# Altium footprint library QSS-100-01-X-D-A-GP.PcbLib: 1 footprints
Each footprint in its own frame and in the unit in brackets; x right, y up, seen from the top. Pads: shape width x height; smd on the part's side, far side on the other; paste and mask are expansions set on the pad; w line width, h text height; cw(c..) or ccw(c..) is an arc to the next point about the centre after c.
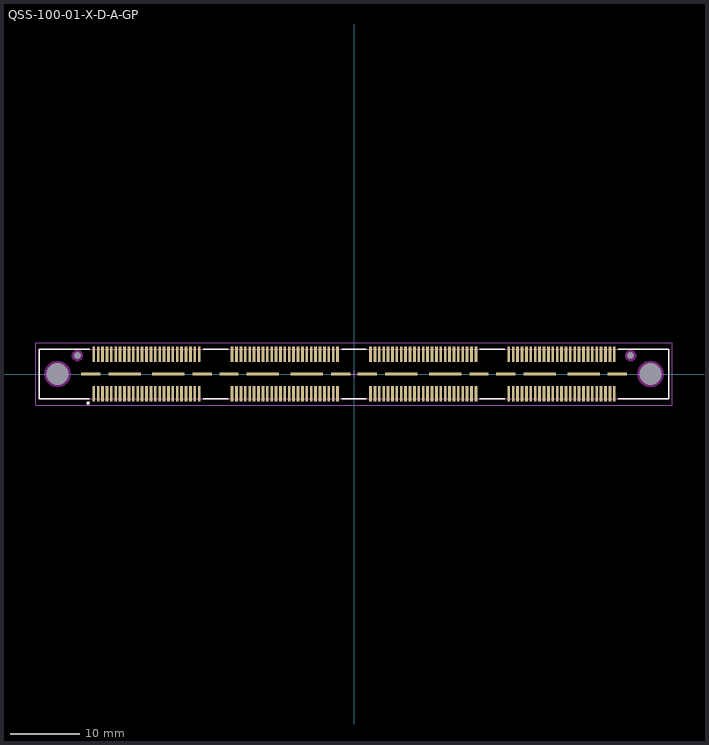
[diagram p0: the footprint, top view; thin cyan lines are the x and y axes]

## QSS-100-01-X-D-A-GP [mm] "0.635mm pitch, 200 pin, high speed socket; w/alignment pins"
height 3.63
pads (220):
  rect 0.4x2.25 smd mask+0: 1(-37.621,-2.865) 2(-37.621,2.865) 3(-36.986,-2.865) 4(-36.986,2.865) 5(-36.351,-2.865) 6(-36.351,2.865) 7(-35.716,-2.865) 8(-35.716,2.865) 9(-35.081,-2.865) 10(-35.081,2.865) 11(-34.446,-2.865) 12(-34.446,2.865) 13(-33.811,-2.865) 14(-33.811,2.865) 15(-33.176,-2.865) 16(-33.176,2.865) 17(-32.541,-2.865) 18(-32.541,2.865) 19(-31.906,-2.865) 20(-31.906,2.865) 21(-31.271,-2.865) 22(-31.271,2.865) 23(-30.636,-2.865) 24(-30.636,2.865) 25(-30.001,-2.865) 26(-30.001,2.865) 27(-29.366,-2.865) 28(-29.366,2.865) 29(-28.731,-2.865) 30(-28.731,2.865) 31(-28.096,-2.865) 32(-28.096,2.865) 33(-27.461,-2.865) 34(-27.461,2.865) 35(-26.826,-2.865) 36(-26.826,2.865) 37(-26.191,-2.865) 38(-26.191,2.865) 39(-25.556,-2.865) 40(-25.556,2.865) 41(-24.921,-2.865) 42(-24.921,2.865) 43(-24.286,-2.865) 44(-24.286,2.865) 45(-23.651,-2.865) 46(-23.651,2.865) 47(-23.016,-2.865) 48(-23.016,2.865) 49(-22.381,-2.865) 50(-22.381,2.865) 51(-17.619,-2.865) 52(-17.619,2.865) 53(-16.984,-2.865) 54(-16.984,2.865) 55(-16.349,-2.865) 56(-16.349,2.865) 57(-15.714,-2.865) 58(-15.714,2.865) 59(-15.079,-2.865) 60(-15.079,2.865) 61(-14.444,-2.865) 62(-14.444,2.865) 63(-13.809,-2.865) 64(-13.809,2.865) 65(-13.174,-2.865) 66(-13.174,2.865) 67(-12.539,-2.865) 68(-12.539,2.865) 69(-11.904,-2.865) 70(-11.904,2.865) 71(-11.269,-2.865) 72(-11.269,2.865) 73(-10.634,-2.865) 74(-10.634,2.865) 75(-9.999,-2.865) 76(-9.999,2.865) 77(-9.364,-2.865) 78(-9.364,2.865) 79(-8.729,-2.865) 80(-8.729,2.865) 81(-8.094,-2.865) 82(-8.094,2.865) 83(-7.459,-2.865) 84(-7.459,2.865) 85(-6.824,-2.865) 86(-6.824,2.865) 87(-6.189,-2.865) 88(-6.189,2.865) 89(-5.554,-2.865) 90(-5.554,2.865) 91(-4.919,-2.865) 92(-4.919,2.865) 93(-4.284,-2.865) 94(-4.284,2.865) 95(-3.649,-2.865) 96(-3.649,2.865) 97(-3.014,-2.865) 98(-3.014,2.865) 99(-2.379,-2.865) 100(-2.379,2.865) 101(2.384,-2.865) 102(2.384,2.865) 103(3.019,-2.865) 104(3.019,2.865) 105(3.654,-2.865) 106(3.654,2.865) 107(4.289,-2.865) 108(4.289,2.865) 109(4.924,-2.865) 110(4.924,2.865) 111(5.559,-2.865) 112(5.559,2.865) 113(6.194,-2.865) 114(6.194,2.865) 115(6.829,-2.865) 116(6.829,2.865) 117(7.464,-2.865) 118(7.464,2.865) 119(8.099,-2.865) 120(8.099,2.865) 121(8.734,-2.865) 122(8.734,2.865) 123(9.369,-2.865) 124(9.369,2.865) 125(10.004,-2.865) 126(10.004,2.865) 127(10.639,-2.865) 128(10.639,2.865) 129(11.274,-2.865) 130(11.274,2.865) 131(11.909,-2.865) 132(11.909,2.865) 133(12.544,-2.865) 134(12.544,2.865) 135(13.179,-2.865) 136(13.179,2.865) 137(13.814,-2.865) 138(13.814,2.865) 139(14.449,-2.865) 140(14.449,2.865) 141(15.084,-2.865) 142(15.084,2.865) 143(15.719,-2.865) 144(15.719,2.865) 145(16.354,-2.865) 146(16.354,2.865) 147(16.989,-2.865) 148(16.989,2.865) 149(17.624,-2.865) 150(17.624,2.865) 151(22.386,-2.865) 152(22.386,2.865) 153(23.021,-2.865) 154(23.021,2.865) 155(23.656,-2.865) 156(23.656,2.865) 157(24.291,-2.865) 158(24.291,2.865) 159(24.926,-2.865) 160(24.926,2.865) 161(25.561,-2.865) 162(25.561,2.865) 163(26.196,-2.865) 164(26.196,2.865) 165(26.831,-2.865) 166(26.831,2.865) 167(27.466,-2.865) 168(27.466,2.865) 169(28.101,-2.865) 170(28.101,2.865) 171(28.736,-2.865) 172(28.736,2.865) 173(29.371,-2.865) 174(29.371,2.865) 175(30.006,-2.865) 176(30.006,2.865) 177(30.641,-2.865) 178(30.641,2.865) 179(31.276,-2.865) 180(31.276,2.865) 181(31.911,-2.865) 182(31.911,2.865) 183(32.546,-2.865) 184(32.546,2.865) 185(33.181,-2.865) 186(33.181,2.865) 187(33.816,-2.865) 188(33.816,2.865) 189(34.451,-2.865) 190(34.451,2.865) 191(35.086,-2.865) 192(35.086,2.865) 193(35.721,-2.865) 194(35.721,2.865) 195(36.356,-2.865) 196(36.356,2.865) 197(36.991,-2.865) 198(36.991,2.865) 199(37.626,-2.865) 200(37.626,2.865)
  rect 2.8x0.45 smd mask+0: 201(-38.066,0) 204(-21.937,0) 205(-18.063,0) 208(-1.934,0) 209(1.939,0) 212(18.068,0) 213(21.942,0) 216(38.071,0)
  rect 4.7x0.45 smd mask+0: 202(-33.176,0) 203(-26.826,0) 206(-13.174,0) 207(-6.824,0) 210(6.829,0) 211(13.179,0) 214(26.831,0) 215(33.181,0)
  round 0.5 hole 3.2 unplated mask+0: 217(-42.86,0) 218(42.86,0)
  round 0.5 hole 1 unplated mask+0: 219(-40.004,2.657) 220(39.996,2.657)
Top Overlay:
  circle w0.25: c-38.45,-4.2 r0.125
  lines w0.2: -38.3,-3.6 -45.5,-3.6 -45.5,3.6 -38.2,3.6 ; -21.8,-3.6 -18.2,-3.6 ; -21.8,3.6 -18.2,3.6 ; -1.8,-3.6 1.8,-3.6 ; -1.8,3.6 1.8,3.6 ; 18.2,-3.6 21.8,-3.6 ; 18.2,3.6 21.8,3.6 ; 38.2,-3.6 45.5,-3.6 45.5,3.6 38.2,3.6
Keep-Out Layer:
  pour cut-out: -39.197,2.657 -39.225,2.866 -39.305,3.06 -39.433,3.228 -39.601,3.356 -39.795,3.436 -40.004,3.464 -40.213,3.436 -40.407,3.356 -40.575,3.228 -40.703,3.06 -40.783,2.866 -40.811,2.657 -40.783,2.448 -40.703,2.254 -40.575,2.086 -40.407,1.958 -40.213,1.878 -40.004,1.85 -39.795,1.878 -39.601,1.958 -39.433,2.086 -39.305,2.254 -39.225,2.448
  pour cut-out: 40.803,2.657 40.775,2.866 40.695,3.06 40.567,3.228 40.399,3.356 40.205,3.436 39.996,3.464 39.787,3.436 39.593,3.356 39.425,3.228 39.297,3.06 39.217,2.866 39.189,2.657 39.217,2.448 39.297,2.254 39.425,2.086 39.593,1.958 39.787,1.878 39.996,1.85 40.205,1.878 40.399,1.958 40.567,2.086 40.695,2.254 40.775,2.448
  pour cut-out: -40.951,0 -40.987,0.372 -41.096,0.731 -41.273,1.061 -41.51,1.35 -41.799,1.587 -42.129,1.764 -42.488,1.873 -42.86,1.909 -43.232,1.873 -43.591,1.764 -43.921,1.587 -44.21,1.35 -44.447,1.061 -44.624,0.731 -44.733,0.372 -44.769,0 -44.733,-0.372 -44.624,-0.731 -44.447,-1.061 -44.21,-1.35 -43.921,-1.587 -43.591,-1.764 -43.232,-1.873 -42.86,-1.909 -42.488,-1.873 -42.129,-1.764 -41.799,-1.587 -41.51,-1.35 -41.273,-1.061 -41.096,-0.731 -40.987,-0.372
  pour cut-out: 44.769,0 44.733,0.372 44.624,0.731 44.447,1.061 44.21,1.35 43.921,1.587 43.591,1.764 43.232,1.873 42.86,1.909 42.488,1.873 42.129,1.764 41.799,1.587 41.51,1.35 41.273,1.061 41.096,0.731 40.987,0.372 40.951,0 40.987,-0.372 41.096,-0.731 41.273,-1.061 41.51,-1.35 41.799,-1.587 42.129,-1.764 42.488,-1.873 42.86,-1.909 43.232,-1.873 43.591,-1.764 43.921,-1.587 44.21,-1.35 44.447,-1.061 44.624,-0.731 44.733,-0.372
Mechanical 12:
  lines w0.001: -45.5,-3.6 45.5,-3.6 45.5,3.6 -45.5,3.6 -45.5,-3.6
Mechanical 13:
  lines w0.1: -45.5,-3.6 45.5,-3.6 45.5,3.6 -45.5,3.6 -45.5,-3.6
  text ".Designator" at 0.254,0.254 h1.52
Mechanical 15:
  lines w0.05: -0.5,0 0.5,0 ; 0,-0.5 0,0.5 ; -46,-4.5 46,-4.5 46,4.5 -46,4.5 -46,-4.5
